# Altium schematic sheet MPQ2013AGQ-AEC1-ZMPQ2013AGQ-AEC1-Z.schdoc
size 127 x 101 mm
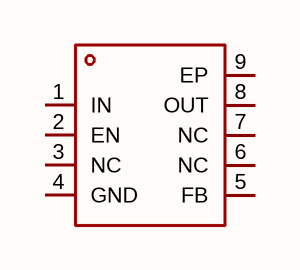
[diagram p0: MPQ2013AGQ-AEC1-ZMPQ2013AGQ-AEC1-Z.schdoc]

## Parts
U?  mpq2013agq-aec1-z  [QFN-8_L3.0-W3.0-P0.65-TL-EP2.5]  (value not drawn)

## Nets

Not connected (* = marked no-connect by the designer): U? 1(IN) 2(EN) 3(NC) 4(GND) 5(FB) 6(NC) 7(NC) 8(OUT) 9(EP)

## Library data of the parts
U? = mpq2013agq-aec1-z: 输出极性:正极;工作电压:40V;输出电压:1.215V~15V;输出电流:150mA;电源纹波抑制比(PSRR):58dB@(100Hz);输出类型:可调;; Manufacturer: MPS(芯源); AddInBom: yes; ModelId: 7d7b0c6373f54773b7915f82dc80757a; ModelTransform: 118.18874,118.11,0,0,0,0,0,0,0; Output Configuration: 正极; Voltage - Supply: 40V; Output Current: 150mA; Voltage Dropout: 1.1V@(150mA); standby current: 3.3uA; Output Type: 可调; Number of Outputs: 1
